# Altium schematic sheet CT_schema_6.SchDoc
size 255 x 245 mm
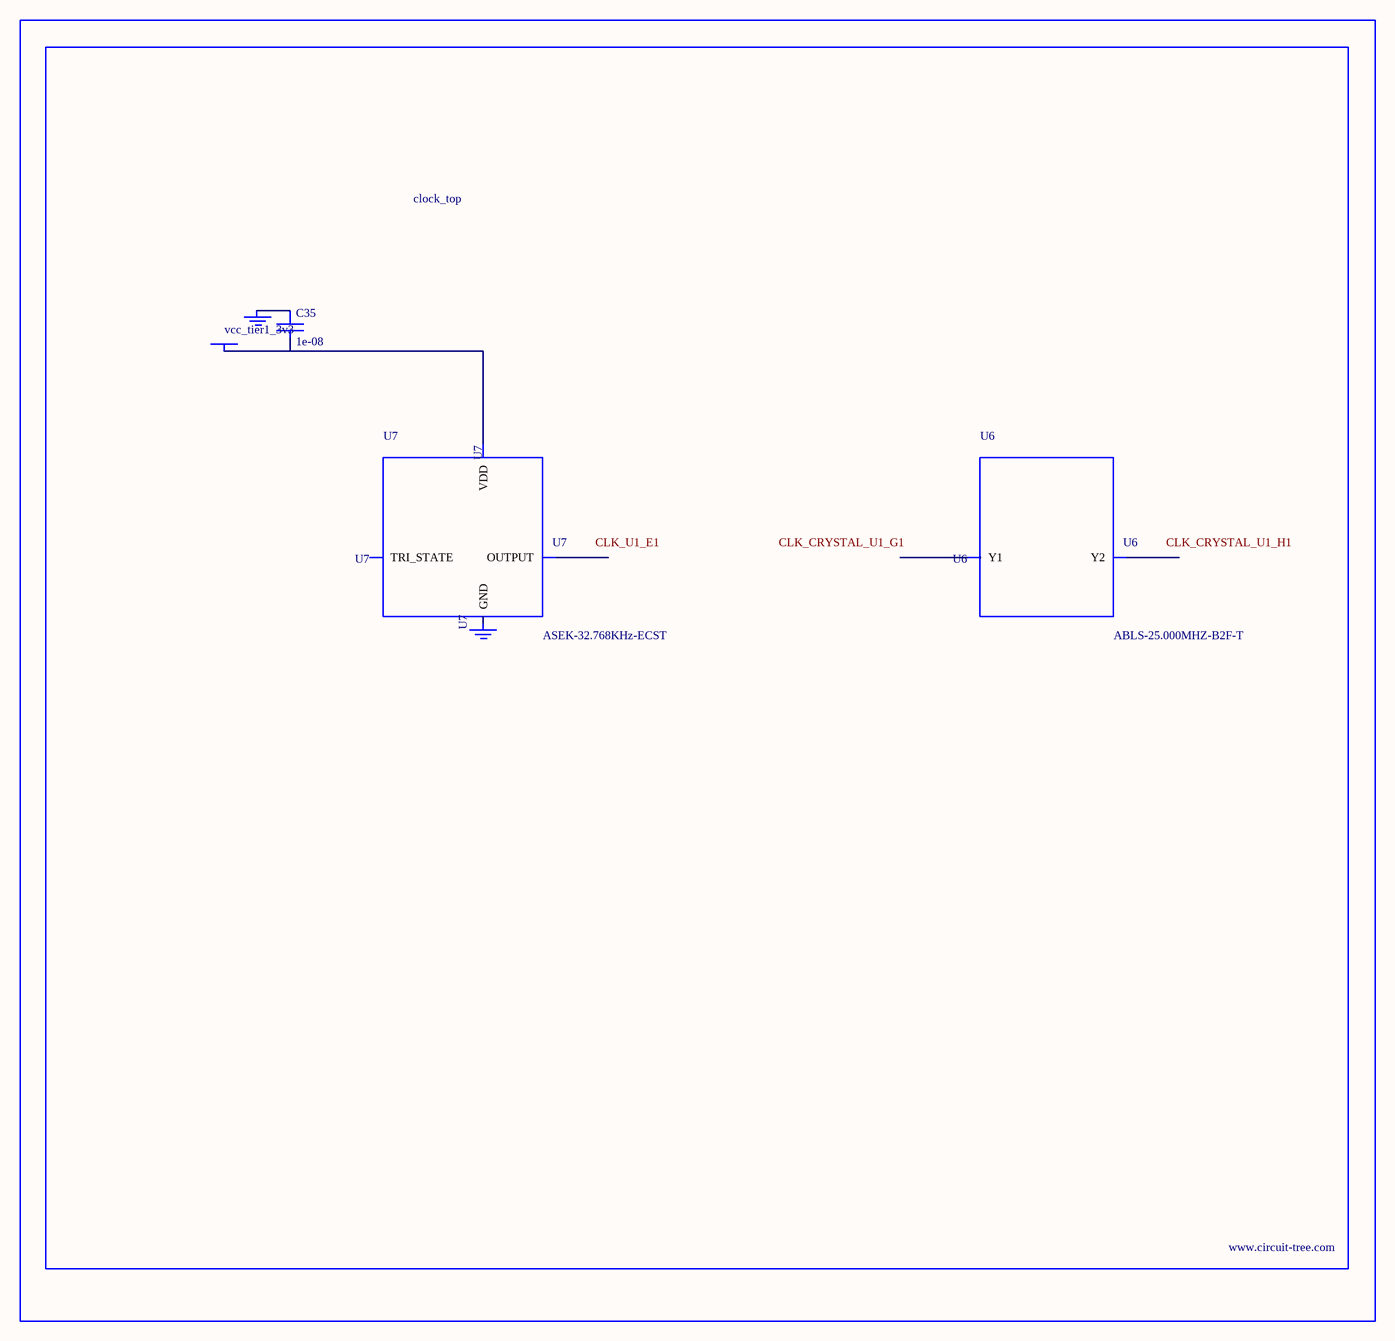
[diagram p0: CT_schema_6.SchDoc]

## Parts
BORDER5  (no value)
C35  1e-08  [C0402]
GND_INSTANCE_5_0  (no value)
GND_INSTANCE_5_1  (no value)
POWER_INSTANCE_5_0  vcc_tier1_3v3
U6  ABLS-25.000MHZ-B2F-T  [ABLS-25.000MHZ-B2F-T]
U7  ASEK-32.768KHz-ECST  [ASEK]

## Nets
NetC35_1: C35.1 GND_INSTANCE_5_0.0(GND)
NetC35_2: C35.2 POWER_INSTANCE_5_0.0(PWR) U7.4(VDD)

Not connected (* = marked no-connect by the designer): GND_INSTANCE_5_1 0(GND); U6 1(Y1) 2(Y2); U7 1(TRI_STATE) 2(GND) 3(OUTPUT)

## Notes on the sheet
- Labels drawn without touching a wire or pin: CLK_CRYSTAL_U1_G1, CLK_CRYSTAL_U1_H1, CLK_U1_E1

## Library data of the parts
BORDER5 = BORDER_PAGE5
C35 = C0402C103K3RAC
GND_INSTANCE_5_0 GND_INSTANCE_5_1 = GND
POWER_INSTANCE_5_0 = PWR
